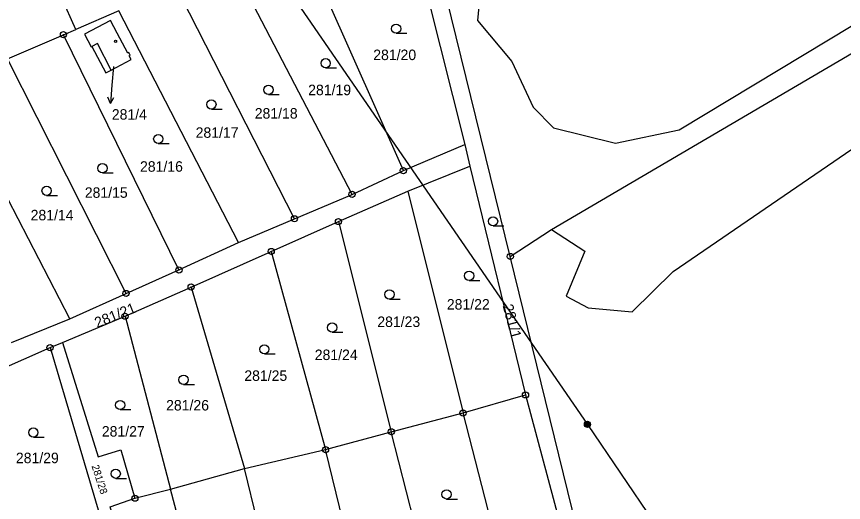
# Model space of a CAD drawing. Extents: x -504988 to -494607, y -1123820 to -1114018.
# Drawn here: x -496854.6 to -496720.6, y -1120371.9 to -1120293.1 of the extents above; entities that cross this region are included whole.
import ezdxf

# ---------------------------------------------------------------- set-up
doc = ezdxf.new("R2010")
doc.units = 0
for name, color, linetype in [('Hranice parcel', 7, 'Continuous'), ('Parcelní čísla', 7, 'Continuous'), ('Pop  PČ popisy', 7, 'Continuous'), ('Poz předměty', 7, 'Continuous'), ('Vnitřní kresba', 7, 'Continuous'), ('Značky bodu BP', 7, 'Continuous'), ('Značky budov', 7, 'Continuous'), ('Značky kultur', 7, 'Continuous')]:
    doc.layers.add(name, color=color, linetype=linetype)

msp = doc.modelspace()

# ---------------------------------------------------------------- linework, layer by layer
at = {"layer": 'Hranice parcel'}
for p, q in [((-496792.38, -1120272.51), (-496781.96, -1120313.9)), ((-496774.59, -1120332.04), (-496787.9, -1120277.81)), ((-496791.91, -1120318.12), (-496808.97, -1120279.67)), ((-496845.03, -1120295.23), (-496849.84, -1120284.29)), ((-496800.24, -1120321.97), (-496819.81, -1120284.35)), ((-496809.57, -1120325.93), (-496828.82, -1120288.24)), ((-496838.03, -1120292.21), (-496845.03, -1120295.23)), ((-496818.66, -1120329.78), (-496838.03, -1120292.21)), ((-496847.02, -1120296.09), (-496845.03, -1120295.23)), ((-496856.11, -1120300.01), (-496847.02, -1120296.09)), ((-496828.29, -1120334.22), (-496847.02, -1120296.09)), ((-496836.87, -1120338.03), (-496856.11, -1120300.01)), ((-496845.96, -1120342.17), (-496865.68, -1120304.13)), ((-496791.91, -1120318.12), (-496781.96, -1120313.9)), ((-496781.96, -1120313.9), (-496781.15, -1120317.4)), ((-496800.24, -1120321.97), (-496791.91, -1120318.12)), ((-496791.21, -1120321.47), (-496781.15, -1120317.4)), ((-496781.15, -1120317.4), (-496772.12, -1120354.48)), ((-496809.57, -1120325.93), (-496800.24, -1120321.97)), ((-496802.44, -1120326.38), (-496791.21, -1120321.47)), ((-496791.21, -1120321.47), (-496782.24, -1120357.41)), ((-496818.66, -1120329.78), (-496809.57, -1120325.93)), ((-496813.34, -1120331.22), (-496802.44, -1120326.38)), ((-496802.44, -1120326.38), (-496793.88, -1120360.46)), ((-496774.59, -1120332.04), (-496767.91, -1120327.65)), ((-496828.29, -1120334.22), (-496818.66, -1120329.78)), ((-496826.33, -1120336.99), (-496813.34, -1120331.22)), ((-496813.34, -1120331.22), (-496804.53, -1120363.36)), ((-496836.87, -1120338.03), (-496828.29, -1120334.22)), ((-496845.96, -1120342.17), (-496836.87, -1120338.03)), ((-496837.04, -1120341.72), (-496826.33, -1120336.99)), ((-496826.33, -1120336.99), (-496817.65, -1120366.4)), ((-496855.42, -1120346.01), (-496845.96, -1120342.17)), ((-496847.18, -1120345.97), (-496837.04, -1120341.72)), ((-496837.04, -1120341.72), (-496829.67, -1120369.74)), ((-496849.19, -1120346.82), (-496847.18, -1120345.97)), ((-496864.07, -1120353.36), (-496849.19, -1120346.82)), ((-496849.19, -1120346.82), (-496841.42, -1120373.13)), ((-496782.24, -1120357.41), (-496772.12, -1120354.48)), ((-496772.12, -1120354.48), (-496762.55, -1120390.05)), ((-496793.88, -1120360.46), (-496782.24, -1120357.41)), ((-496773.32, -1120392.1), (-496782.24, -1120357.41)), ((-496804.53, -1120363.36), (-496793.88, -1120360.46)), ((-496785.34, -1120393.88), (-496793.88, -1120360.46)), ((-496817.65, -1120366.4), (-496804.53, -1120363.36)), ((-496796.7, -1120395.67), (-496804.53, -1120363.36)), ((-496829.67, -1120369.74), (-496817.65, -1120366.4)), ((-496810.1, -1120397.58), (-496817.65, -1120366.4)), ((-496835.44, -1120371.23), (-496829.67, -1120369.74)), ((-496822, -1120398.82), (-496829.67, -1120369.74))]:
    msp.add_line(p, q, dxfattribs=at)
for points in [[(-496787.9, -1120277.81), (-496778.84, -1120282.34), (-496779.91, -1120293.77), (-496774.36, -1120300.42), (-496770.89, -1120307.84), (-496767.59, -1120311.18), (-496757.55, -1120313.67), (-496747.19, -1120311.49), (-496678.82, -1120270.21), (-496629.45, -1120234.43), (-496598.89, -1120218.03), (-496545.47, -1120201.71), (-496541.46, -1120201.26)], [(-496767.91, -1120327.65), (-496676.63, -1120274.07), (-496589.59, -1120216.75), (-496523.62, -1120205.61)], [(-496767.91, -1120327.65), (-496762.51, -1120331.18), (-496765.54, -1120338.5), (-496761.94, -1120340.39), (-496754.82, -1120341.01), (-496748.17, -1120334.46), (-496690.23, -1120294.81), (-496597.45, -1120237.67), (-496580.84, -1120229.75), (-496564.4, -1120224.77), (-496546.71, -1120221.67), (-496531.71, -1120222.02), (-496517.86, -1120224.07), (-496514.94, -1120222.65), (-496512.85, -1120219.63)], [(-496842.53, -1120298.05), (-496842.42, -1120297.99), (-496840.16, -1120302.29), (-496839.28, -1120301.83), (-496836.04, -1120300.11), (-496836.38, -1120299.5), (-496836.2, -1120299.4), (-496836.42, -1120298.98), (-496836.6, -1120299.08), (-496838.34, -1120295.82), (-496839.41, -1120293.79), (-496843.6, -1120296), (-496842.53, -1120298.05)], [(-496747.78, -1120433.39), (-496762.37, -1120381.81), (-496774.59, -1120332.04)], [(-496847.18, -1120345.97), (-496841.41, -1120364.5), (-496837.7, -1120363.39), (-496835.44, -1120371.23)], [(-496831.83, -1120399.85), (-496839.46, -1120372.61), (-496835.44, -1120371.23)]]:
    msp.add_lwpolyline(points, dxfattribs=at)
at = {"layer": 'Pop  PČ popisy'}
for p, q in [((-496838.92, -1120301.26), (-496839.16, -1120304.25)), ((-496839.16, -1120304.25), (-496839.42, -1120307.24)), ((-496839.42, -1120307.24), (-496839.83, -1120306.2)), ((-496839.42, -1120307.24), (-496838.84, -1120306.29))]:
    msp.add_line(p, q, dxfattribs=at)
at = {"layer": 'Poz předměty'}
for p, q in [((-496831.27, -1120258.77), (-496762.08, -1120359.26)), ((-496762.08, -1120359.26), (-496702.44, -1120446.88))]:
    msp.add_line(p, q, dxfattribs=at)
for radius in [0.5, 0.4, 0.3, 0.2, 0.1]:
    msp.add_circle((-496762.08, -1120359.26), radius, dxfattribs=at)
at = {"layer": 'Vnitřní kresba'}
for p, q in [((-496841.52, -1120297.51), (-496842.42, -1120297.99)), ((-496839.28, -1120301.83), (-496841.52, -1120297.51))]:
    msp.add_line(p, q, dxfattribs=at)
at = {"layer": 'Značky bodu BP'}
for centre, radius in [((-496847.02, -1120296.09), 0.5), ((-496847.02, -1120296.09), 0.0303), ((-496791.91, -1120318.12), 0.5), ((-496791.91, -1120318.12), 0.0303), ((-496800.24, -1120321.97), 0.5), ((-496800.24, -1120321.97), 0.0303), ((-496809.57, -1120325.93), 0.5), ((-496809.57, -1120325.93), 0.0303), ((-496802.44, -1120326.38), 0.5), ((-496802.44, -1120326.38), 0.0303), ((-496813.34, -1120331.22), 0.5), ((-496813.34, -1120331.22), 0.0303), ((-496774.59, -1120332.04), 0.5), ((-496774.59, -1120332.04), 0.0303), ((-496828.29, -1120334.22), 0.5), ((-496828.29, -1120334.22), 0.0303), ((-496826.33, -1120336.99), 0.5), ((-496826.33, -1120336.99), 0.0303), ((-496836.87, -1120338.03), 0.5), ((-496836.87, -1120338.03), 0.0303), ((-496837.04, -1120341.72), 0.5), ((-496837.04, -1120341.72), 0.0303), ((-496849.19, -1120346.82), 0.5), ((-496849.19, -1120346.82), 0.0303), ((-496772.12, -1120354.48), 0.5), ((-496772.12, -1120354.48), 0.0303), ((-496782.24, -1120357.41), 0.5), ((-496782.24, -1120357.41), 0.0303), ((-496793.88, -1120360.46), 0.5), ((-496793.88, -1120360.46), 0.0303), ((-496804.53, -1120363.36), 0.5), ((-496804.53, -1120363.36), 0.0303), ((-496835.44, -1120371.23), 0.5), ((-496835.44, -1120371.23), 0.0303)]:
    msp.add_circle(centre, radius, dxfattribs=at)
at = {"layer": 'Značky budov'}
msp.add_circle((-496838.57, -1120297.17), 0.175, dxfattribs=at)
at = {"layer": 'Značky kultur'}
for p, q in [((-496793.1, -1120295.86), (-496791.35, -1120295.86)), ((-496804.52, -1120301.46), (-496802.77, -1120301.46)), ((-496813.78, -1120305.77), (-496812.03, -1120305.77)), ((-496823.04, -1120308.14), (-496821.29, -1120308.14)), ((-496831.65, -1120313.74), (-496829.9, -1120313.74)), ((-496840.7, -1120318.48), (-496838.95, -1120318.48)), ((-496849.75, -1120322.14), (-496848, -1120322.14)), ((-496777.38, -1120327.09), (-496775.63, -1120327.09)), ((-496781.26, -1120335.92), (-496779.51, -1120335.92)), ((-496794.18, -1120338.94), (-496792.43, -1120338.94)), ((-496803.46, -1120344.31), (-496801.71, -1120344.31)), ((-496814.45, -1120347.84), (-496812.7, -1120347.84)), ((-496827.55, -1120352.78), (-496825.8, -1120352.78)), ((-496837.83, -1120356.87), (-496836.08, -1120356.87)), ((-496851.9, -1120361.33), (-496850.15, -1120361.33)), ((-496838.55, -1120368.01), (-496836.8, -1120368.01)), ((-496784.91, -1120371.36), (-496783.16, -1120371.36))]:
    msp.add_line(p, q, dxfattribs=at)
for centre in [(-496793.1, -1120295.11), (-496804.52, -1120300.71), (-496813.78, -1120305.02), (-496823.04, -1120307.39), (-496831.65, -1120312.99), (-496840.7, -1120317.73), (-496849.75, -1120321.39), (-496777.38, -1120326.34), (-496781.26, -1120335.17), (-496794.18, -1120338.19), (-496803.46, -1120343.56), (-496814.45, -1120347.09), (-496827.55, -1120352.03), (-496837.83, -1120356.12), (-496851.9, -1120360.58), (-496838.55, -1120367.26), (-496784.91, -1120370.61)]:
    msp.add_circle(centre, 0.75, dxfattribs=at)

# ---------------------------------------------------------------- texts
at = {"layer": 'Parcelní čísla'}
for s, p in [('281/20', (-496796.8, -1120300.2)), ('281/19', (-496807.35, -1120305.89)), ('281/4', (-496839.18, -1120309.86)), ('281/18', (-496816.01, -1120309.69)), ('281/17', (-496825.59, -1120312.8)), ('281/16', (-496834.61, -1120318.3)), ('281/15', (-496843.56, -1120322.53)), ('281/14', (-496852.34, -1120326.18)), ('281/22', (-496784.87, -1120340.65)), ('281/23', (-496796.14, -1120343.47)), ('281/24', (-496806.28, -1120348.83)), ('281/25', (-496817.7, -1120352.21)), ('281/26', (-496830.38, -1120357.01)), ('281/27', (-496840.8, -1120361.24)), ('281/29', (-496854.73, -1120365.55))]:
    msp.add_text(s, height=1.7, dxfattribs=at).set_placement(p)
for s, height, rotation, p in [('281/21', 1.7, 22, (-496841.56, -1120343.65)), ('281/1', 1.7, 285, (-496775.84, -1120340.02)), ('281/28', 1.2, 288, (-496842.48, -1120366.02))]:
    msp.add_text(s, height=height, rotation=rotation, dxfattribs=at).set_placement(p)

doc.saveas('drawing.dxf')
